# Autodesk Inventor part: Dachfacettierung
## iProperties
Created: 2009-02
Part Number: Dachfacettierung
Document SubType Name: Modeling
Designer: Hans-Jürgen Eicke
Author: Hans-Jürgen Eicke
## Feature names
1. Erhebung5
2. Spiegeln4 [Mirror]
